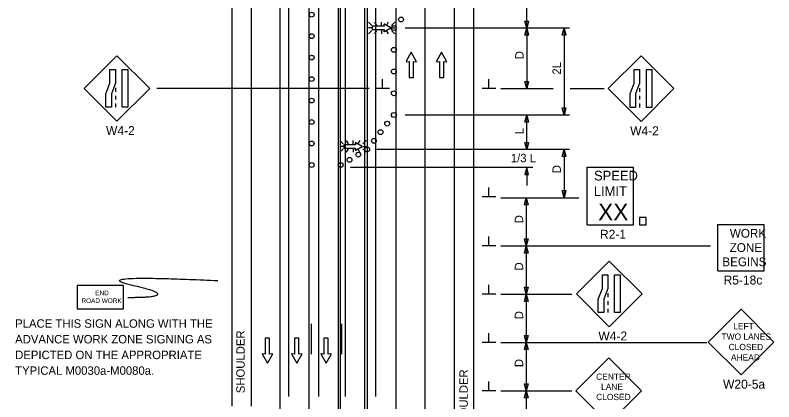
# Model space of a CAD drawing. Extents: x 16732 to 18475, y 6994 to 8262.
# Drawn here: x 16737 to 17365, y 7429 to 7749 of the extents above; entities that cross this region are included whole.
import ezdxf

# ---------------------------------------------------------------- set-up
doc = ezdxf.new("R2010")
doc.units = 0
for name, color, linetype in [('ALI_LEGAL_EX', 7, 'Continuous'), ('MT_SCRATCH_LEVEL_E', 7, 'Continuous'), ('PAVT_EDGE_EX', 7, 'Continuous'), ('TRAFFIC_SIGNS_PR', 7, 'Continuous'), ('TYPICAL_TEXT_DIMEN_PR', 7, 'Continuous')]:
    doc.layers.add(name, color=color, linetype=linetype)

msp = doc.modelspace()

# ---------------------------------------------------------------- linework, layer by layer
at = {"layer": 'ALI_LEGAL_EX'}
for p, q in [((16956.31, 7350.48), (16956.31, 8147.76)), ((16980.31, 7350.48), (16980.31, 8147.76)), ((17006.31, 7350.48), (17006.31, 8147.76)), ((17026.31, 7350.48), (17026.31, 8147.76)), ((17052.31, 7350.48), (17052.31, 8147.76)), ((17076.31, 7350.48), (17076.31, 8147.76))]:
    msp.add_line(p, q, dxfattribs=at)
for points in [[(16956.31, 7650.48), (16956.31, 7675.48)], [(16980.31, 7650.48), (16980.31, 7675.48)], [(17006.31, 7650.48), (17006.31, 7675.48)], [(17026.31, 7650.48), (17026.31, 7675.48)], [(17076.31, 7650.48), (17076.31, 7675.48)], [(16956.31, 7550.48), (16956.31, 7575.48)], [(16980.31, 7550.48), (16980.31, 7575.48)], [(17006.31, 7550.48), (17006.31, 7575.48)], [(17026.31, 7550.48), (17026.31, 7575.48)], [(17052.31, 7550.48), (17052.31, 7575.48)], [(17076.31, 7550.48), (17076.31, 7575.48)], [(16956.31, 7450.48), (16956.31, 7475.48)], [(16980.31, 7450.48), (16980.31, 7475.48)], [(17006.31, 7450.48), (17006.31, 7475.48)], [(17026.31, 7450.48), (17026.31, 7475.48)], [(17052.31, 7450.48), (17052.31, 7475.48)], [(17076.31, 7450.48), (17076.31, 7475.48)]]:
    msp.add_lwpolyline(points, dxfattribs=at)
at = {"layer": 'MT_SCRATCH_LEVEL_E'}
for p, q in [((17064.83, 7718.14), (17060.72, 7710.9)), ((17064.83, 7718.14), (17060.72, 7710.9)), ((17068.98, 7710.9), (17064.83, 7718.14)), ((17068.98, 7710.9), (17064.83, 7718.14)), ((17089.92, 7718.14), (17085.81, 7710.9)), ((17089.92, 7718.14), (17085.81, 7710.9)), ((17094.07, 7710.9), (17089.92, 7718.14)), ((17094.07, 7710.9), (17089.92, 7718.14)), ((17061.2, 7710.21), (17062.98, 7710.53)), ((17061.2, 7710.21), (17062.98, 7710.53)), ((17062.98, 7710.53), (17062.98, 7697.27)), ((17062.98, 7710.53), (17062.98, 7697.27)), ((17066.72, 7697.27), (17066.72, 7710.53)), ((17066.72, 7710.53), (17068.5, 7710.21)), ((17066.72, 7697.27), (17066.72, 7710.53)), ((17066.72, 7710.53), (17068.5, 7710.21)), ((17086.29, 7710.21), (17088.07, 7710.53)), ((17086.29, 7710.21), (17088.07, 7710.53)), ((17088.07, 7710.53), (17088.07, 7697.27)), ((17088.07, 7710.53), (17088.07, 7697.27)), ((17091.81, 7697.27), (17091.81, 7710.53)), ((17091.81, 7710.53), (17093.59, 7710.21)), ((17091.81, 7697.27), (17091.81, 7710.53)), ((17091.81, 7710.53), (17093.59, 7710.21)), ((17062.98, 7697.27), (17066.72, 7697.27)), ((17062.98, 7697.27), (17066.72, 7697.27)), ((17088.07, 7697.27), (17091.81, 7697.27)), ((17088.07, 7697.27), (17091.81, 7697.27)), ((16947.65, 7481.37), (16943.91, 7481.37)), ((16943.91, 7481.37), (16943.91, 7468.11)), ((16947.65, 7481.37), (16943.91, 7481.37)), ((16943.91, 7481.37), (16943.91, 7468.11)), ((16947.65, 7468.11), (16947.65, 7481.37)), ((16947.65, 7468.11), (16947.65, 7481.37)), ((16971.91, 7481.37), (16968.16, 7481.37)), ((16968.16, 7481.37), (16968.16, 7468.11)), ((16971.91, 7481.37), (16968.16, 7481.37)), ((16968.16, 7481.37), (16968.16, 7468.11)), ((16971.91, 7468.11), (16971.91, 7481.37)), ((16971.91, 7468.11), (16971.91, 7481.37)), ((16996.16, 7481.37), (16992.42, 7481.37)), ((16992.42, 7481.37), (16992.42, 7468.11)), ((16996.16, 7481.37), (16992.42, 7481.37)), ((16992.42, 7481.37), (16992.42, 7468.11)), ((16996.16, 7468.11), (16996.16, 7481.37)), ((16996.16, 7468.11), (16996.16, 7481.37)), ((16943.91, 7468.11), (16942.13, 7468.43)), ((16943.91, 7468.11), (16942.13, 7468.43)), ((16949.43, 7468.43), (16947.65, 7468.11)), ((16949.43, 7468.43), (16947.65, 7468.11)), ((16968.16, 7468.11), (16966.39, 7468.43)), ((16968.16, 7468.11), (16966.39, 7468.43)), ((16973.68, 7468.43), (16971.91, 7468.11)), ((16973.68, 7468.43), (16971.91, 7468.11)), ((16992.42, 7468.11), (16990.64, 7468.43)), ((16992.42, 7468.11), (16990.64, 7468.43)), ((16997.94, 7468.43), (16996.16, 7468.11)), ((16997.94, 7468.43), (16996.16, 7468.11)), ((16941.65, 7467.74), (16945.8, 7460.5)), ((16941.65, 7467.74), (16945.8, 7460.5)), ((16945.8, 7460.5), (16949.91, 7467.74)), ((16945.8, 7460.5), (16949.91, 7467.74)), ((16965.91, 7467.74), (16970.05, 7460.5)), ((16965.91, 7467.74), (16970.05, 7460.5)), ((16970.05, 7460.5), (16974.16, 7467.74)), ((16970.05, 7460.5), (16974.16, 7467.74)), ((16990.16, 7467.74), (16994.31, 7460.5)), ((16990.16, 7467.74), (16994.31, 7460.5)), ((16994.31, 7460.5), (16998.42, 7467.74)), ((16994.31, 7460.5), (16998.42, 7467.74))]:
    msp.add_line(p, q, dxfattribs=at)
for centre, start, end in [((17061.13, 7710.67), 150.42484, 279.96381), ((17061.13, 7710.67), 150.42484, 279.96381), ((17068.57, 7710.67), 260.03619, 29.77312), ((17068.57, 7710.67), 260.03619, 29.77312), ((17086.22, 7710.67), 150.42484, 279.96381), ((17086.22, 7710.67), 150.42484, 279.96381), ((17093.66, 7710.67), 260.03619, 29.77312), ((17093.66, 7710.67), 260.03619, 29.77312), ((16942.06, 7467.97), 80.03619, 209.77312), ((16942.06, 7467.97), 80.03619, 209.77312), ((16949.5, 7467.97), 330.42484, 99.96381), ((16949.5, 7467.97), 330.42484, 99.96381), ((16966.32, 7467.97), 80.03619, 209.77312), ((16966.32, 7467.97), 80.03619, 209.77312), ((16973.76, 7467.97), 330.42484, 99.96381), ((16973.76, 7467.97), 330.42484, 99.96381), ((16990.57, 7467.97), 80.03619, 209.77312), ((16990.57, 7467.97), 80.03619, 209.77312), ((16998.01, 7467.97), 330.42484, 99.96381), ((16998.01, 7467.97), 330.42484, 99.96381)]:
    msp.add_arc(centre, 0.463, start, end, dxfattribs=at)
at = {"layer": 'PAVT_EDGE_EX'}
for p, q in [((16963.15, 8262.34), (16963.15, 7433.15)), ((16988.15, 8262.34), (16988.15, 7433.15)), ((17010.15, 8262.34), (17010.15, 7433.15)), ((17035.15, 8262.34), (17035.15, 7433.15)), ((16916.31, 8206.5), (16916.31, 7425.05)), ((16932.31, 8206.5), (16932.31, 7425.05)), ((17004.31, 8206.5), (17004.31, 7350.48)), ((17028.31, 8206.5), (17028.31, 7350.48)), ((17100.31, 8206.5), (17100.31, 7350.48)), ((17116.31, 8206.5), (17116.31, 7350.48))]:
    msp.add_line(p, q, dxfattribs=at)
for points in [[(16982.24, 7468.16), (16982.24, 7493.16)], [(17007.24, 7468.16), (17007.24, 7493.16)]]:
    msp.add_lwpolyline(points, dxfattribs=at)
at = {"layer": 'TRAFFIC_SIGNS_PR'}
for p, q in [((17032.16, 7740.31), (17029.33, 7743.13)), ((17032.16, 7738.28), (17029.33, 7738.28)), ((17034.45, 7743.13), (17036.08, 7740.31)), ((17040.24, 7740.31), (17040.24, 7743.13)), ((17045.71, 7743.13), (17044.5, 7741.03)), ((17051.15, 7743.12), (17048.33, 7740.31)), ((17048.33, 7738.28), (17051.15, 7738.28)), ((17032.16, 7736.24), (17029.33, 7733.42)), ((17036.11, 7736.24), (17034.48, 7733.42)), ((17040.24, 7736.24), (17040.24, 7733.42)), ((17044.42, 7735.61), (17045.69, 7733.42)), ((17051.15, 7733.43), (17048.33, 7736.24)), ((16821.33, 7715.27), (16794.17, 7688.12)), ((16848.48, 7688.12), (16821.33, 7715.27)), ((17254.9, 7715.17), (17227.75, 7688.02)), ((17282.06, 7688.02), (17254.9, 7715.17)), ((16794.17, 7688.12), (16821.33, 7660.96)), ((16820.08, 7688.61), (16820.08, 7685.41)), ((16821.33, 7660.96), (16848.48, 7688.12)), ((17227.75, 7688.02), (17254.9, 7660.87)), ((17253.66, 7688.51), (17253.66, 7685.31)), ((17254.9, 7660.87), (17282.06, 7688.02)), ((16820.08, 7682.21), (16820.08, 7679.01)), ((17253.66, 7682.11), (17253.66, 7678.91)), ((16820.08, 7675.81), (16820.08, 7672.61)), ((17253.66, 7675.71), (17253.66, 7672.51)), ((17008.58, 7642.22), (17005.75, 7645.04)), ((17010.87, 7645.04), (17012.5, 7642.22)), ((17016.66, 7642.22), (17016.66, 7645.04)), ((17022.13, 7645.04), (17020.92, 7642.95)), ((17027.56, 7645.04), (17024.74, 7642.22)), ((17008.58, 7640.19), (17005.75, 7640.19)), ((17008.58, 7638.16), (17005.75, 7635.34)), ((17012.53, 7638.16), (17010.9, 7635.34)), ((17016.66, 7638.16), (17016.66, 7635.34)), ((17024.74, 7640.19), (17027.56, 7640.19)), ((17027.56, 7635.34), (17024.74, 7638.16)), ((17020.84, 7637.52), (17022.1, 7635.34)), ((17210.25, 7623.1), (17248.65, 7623.1)), ((17210.25, 7575.1), (17210.25, 7623.1)), ((17248.65, 7575.1), (17248.65, 7623.1)), ((17210.25, 7575.1), (17248.65, 7575.1)), ((17318.32, 7537.23), (17318.32, 7575.63)), ((17318.32, 7575.63), (17356.72, 7575.63)), ((17356.72, 7537.23), (17356.72, 7575.63)), ((17228.62, 7545.16), (17201.47, 7518.01)), ((17255.77, 7518.01), (17228.62, 7545.16)), ((17318.32, 7537.23), (17356.72, 7537.23)), ((17227.37, 7518.5), (17227.37, 7515.3)), ((17201.47, 7518.01), (17228.62, 7490.86)), ((17227.37, 7512.1), (17227.37, 7508.9)), ((17228.62, 7490.86), (17255.77, 7518.01)), ((17227.37, 7505.7), (17227.37, 7502.5)), ((17337.57, 7505.24), (17310.41, 7478.09)), ((17364.72, 7478.09), (17337.57, 7505.24)), ((17310.41, 7478.09), (17337.57, 7450.93)), ((17337.57, 7450.93), (17364.72, 7478.09)), ((17228.16, 7464.98), (17201, 7437.82)), ((17255.31, 7437.82), (17228.16, 7464.98)), ((17201, 7437.82), (17228.16, 7410.67)), ((17228.16, 7410.67), (17255.31, 7437.82))]:
    msp.add_line(p, q, dxfattribs=at)
for points in [[(17042.07, 7740.96), (17042.3, 7739.66), (17032.58, 7739.66), (17032.58, 7736.92), (17042.3, 7736.92), (17042.07, 7735.61)], [(17042.57, 7735.26), (17047.88, 7738.28), (17042.57, 7741.32)], [(17018.49, 7642.87), (17018.72, 7641.58), (17008.99, 7641.58), (17008.99, 7638.83), (17018.72, 7638.83), (17018.49, 7637.53)], [(17018.99, 7637.18), (17024.3, 7640.19), (17018.99, 7643.23)]]:
    msp.add_lwpolyline(points, dxfattribs=at)
for points in [[(16820.08, 7703.85), (16820.08, 7692.67), (16816.74, 7683.79), (16816.74, 7672.61), (16812.24, 7672.61), (16812.24, 7683.79), (16815.59, 7692.67), (16815.59, 7703.85)], [(16830.22, 7703.85), (16830.22, 7672.61), (16825.72, 7672.61), (16825.72, 7703.85)], [(17253.66, 7703.76), (17253.66, 7692.58), (17250.31, 7683.69), (17250.31, 7672.51), (17245.82, 7672.51), (17245.82, 7683.69), (17249.16, 7692.58), (17249.16, 7703.76)], [(17263.79, 7703.76), (17263.79, 7672.51), (17259.3, 7672.51), (17259.3, 7703.76)], [(17253.66, 7575.1), (17259.25, 7575.1), (17259.25, 7581.27), (17253.66, 7581.27)], [(17227.37, 7533.75), (17227.37, 7522.56), (17224.03, 7513.68), (17224.03, 7502.5), (17219.54, 7502.5), (17219.54, 7513.68), (17222.88, 7522.56), (17222.88, 7533.75)], [(17237.51, 7533.75), (17237.51, 7502.5), (17233.02, 7502.5), (17233.02, 7533.75)], [(16788.41, 7505.76), (16826.81, 7505.76), (16826.81, 7524.96), (16788.41, 7524.96)]]:
    msp.add_lwpolyline(points, close=True, dxfattribs=at)
for centre in [(16982.41, 7749.34), (17056.38, 7745.35), (17050.38, 7738.2), (16982.41, 7731.54), (17050.38, 7720.2), (16982.41, 7713.75), (17050.38, 7702.2), (16982.41, 7695.95), (17050.38, 7684.2), (16982.41, 7678.16), (17050.38, 7666.2), (16982.41, 7660.36), (17044.88, 7659.07), (17039.39, 7651.94), (16982.41, 7642.57), (17033.89, 7644.82), (17028.39, 7637.69), (17021.06, 7633.39), (16982.41, 7624.77), (17006.41, 7624.77), (17013.73, 7629.08)]:
    msp.add_circle(centre, 2, dxfattribs=at)
for centre, start, end in [((17042.4, 7741.02), 61.48329, 189.95933), ((17042.4, 7735.56), 170.73078, 298.89165), ((17018.82, 7642.93), 61.48329, 189.95933), ((17018.82, 7637.48), 170.73078, 298.89165)]:
    msp.add_arc(centre, 0.341, start, end, dxfattribs=at)
msp.add_open_spline([(16830.4, 7515.13), (16877.64, 7515.13), (16792.62, 7534.48), (16904.91, 7528.99)], degree=2, dxfattribs=at)
at = {"layer": 'TYPICAL_TEXT_DIMEN_PR'}
for p, q in [((17160.31, 7738.19), (17160.31, 7768.77)), ((17195.67, 7738.19), (17059.67, 7738.19)), ((17160.31, 7738.19), (17158.74, 7744.06)), ((17158.74, 7744.06), (17160.31, 7744.06)), ((17158.74, 7732.33), (17160.31, 7738.19)), ((17160.31, 7744.06), (17161.88, 7744.06)), ((17161.88, 7744.06), (17160.31, 7738.19)), ((17160.31, 7738.19), (17160.31, 7688.19)), ((17160.31, 7738.19), (17161.88, 7732.33)), ((17189.59, 7732.33), (17191.16, 7738.19)), ((17191.16, 7738.19), (17191.16, 7666.2)), ((17191.16, 7738.19), (17192.73, 7732.33)), ((17160.31, 7732.33), (17158.74, 7732.33)), ((17161.88, 7732.33), (17160.31, 7732.33)), ((17191.16, 7732.33), (17189.59, 7732.33)), ((17192.73, 7732.33), (17191.16, 7732.33)), ((17041.1, 7688.19), (17041.1, 7695.98)), ((17129.06, 7688.19), (17129.06, 7695.98)), ((17160.31, 7688.19), (17158.74, 7694.06)), ((17158.74, 7694.06), (17160.31, 7694.06)), ((17160.31, 7694.06), (17161.88, 7694.06)), ((17161.88, 7694.06), (17160.31, 7688.19)), ((17030.02, 7688.19), (16854.31, 7688.19)), ((17046.73, 7688.19), (17035.48, 7688.19)), ((17134.69, 7688.19), (17123.44, 7688.19)), ((17138.94, 7688.19), (17182.14, 7688.19)), ((17196.21, 7688.19), (17224.34, 7688.19)), ((17191.16, 7666.2), (17189.59, 7672.07)), ((17189.59, 7672.07), (17191.16, 7672.07)), ((17191.16, 7672.07), (17192.73, 7672.07)), ((17192.73, 7672.07), (17191.16, 7666.2)), ((17195.67, 7666.2), (17059.67, 7666.2)), ((17158.74, 7660.34), (17160.31, 7666.2)), ((17160.31, 7637.69), (17160.31, 7666.2)), ((17160.31, 7666.2), (17161.88, 7660.34)), ((17160.31, 7660.34), (17158.74, 7660.34)), ((17161.88, 7660.34), (17160.31, 7660.34)), ((17195.67, 7637.69), (17036.26, 7637.69)), ((17160.31, 7637.69), (17158.74, 7643.55)), ((17158.74, 7643.55), (17160.31, 7643.55)), ((17160.31, 7643.55), (17161.88, 7643.55)), ((17161.88, 7643.55), (17160.31, 7637.69)), ((17189.59, 7631.83), (17191.16, 7637.69)), ((17191.16, 7637.69), (17192.73, 7631.83)), ((17191.16, 7637.69), (17191.16, 7597.69)), ((17191.16, 7631.83), (17189.59, 7631.83)), ((17192.73, 7631.83), (17191.16, 7631.83)), ((17165.31, 7622.77), (17014.53, 7622.77)), ((17160.31, 7622.77), (17158.74, 7616.91)), ((17160.31, 7622.77), (17160.31, 7607.85)), ((17161.88, 7616.91), (17160.31, 7622.77)), ((17158.74, 7616.91), (17160.31, 7616.91)), ((17160.31, 7616.91), (17161.88, 7616.91)), ((17129.06, 7598.34), (17129.06, 7606.13)), ((17191.16, 7597.69), (17189.59, 7603.55)), ((17189.59, 7603.55), (17191.16, 7603.55)), ((17191.16, 7603.55), (17192.73, 7603.55)), ((17192.73, 7603.55), (17191.16, 7597.69)), ((17134.69, 7598.34), (17123.44, 7598.34)), ((17138.94, 7597.69), (17203.28, 7597.69)), ((17158.37, 7591.83), (17159.94, 7597.69)), ((17159.94, 7597.69), (17159.94, 7557.69)), ((17159.94, 7597.69), (17161.51, 7591.83)), ((17159.94, 7591.83), (17158.37, 7591.83)), ((17161.51, 7591.83), (17159.94, 7591.83)), ((17129.06, 7557.69), (17129.06, 7565.48)), ((17159.94, 7557.69), (17158.37, 7563.55)), ((17158.37, 7563.55), (17159.94, 7563.55)), ((17159.94, 7563.55), (17161.51, 7563.55)), ((17161.51, 7563.55), (17159.94, 7557.69)), ((17134.69, 7557.69), (17123.44, 7557.69)), ((17138.94, 7557.69), (17312.45, 7557.69)), ((17158.37, 7551.83), (17159.94, 7557.69)), ((17159.94, 7557.69), (17159.94, 7517.69)), ((17159.94, 7557.69), (17161.51, 7551.83)), ((17159.94, 7551.83), (17158.37, 7551.83)), ((17161.51, 7551.83), (17159.94, 7551.83)), ((17129.06, 7517.69), (17129.06, 7525.48)), ((17159.94, 7517.69), (17158.37, 7523.55)), ((17158.37, 7523.55), (17159.94, 7523.55)), ((17159.94, 7523.55), (17161.51, 7523.55)), ((17161.51, 7523.55), (17159.94, 7517.69)), ((17134.69, 7517.69), (17123.44, 7517.69)), ((17138.94, 7517.69), (17197.62, 7517.69)), ((17158.37, 7511.83), (17159.94, 7517.69)), ((17159.94, 7517.69), (17159.94, 7477.69)), ((17159.94, 7517.69), (17161.51, 7511.83)), ((17159.94, 7511.83), (17158.37, 7511.83)), ((17161.51, 7511.83), (17159.94, 7511.83)), ((17129.06, 7477.69), (17129.06, 7485.48)), ((17159.94, 7477.69), (17158.37, 7483.55)), ((17158.37, 7483.55), (17159.94, 7483.55)), ((17159.94, 7483.55), (17161.51, 7483.55)), ((17161.51, 7483.55), (17159.94, 7477.69)), ((17134.69, 7477.69), (17123.44, 7477.69)), ((17138.94, 7477.69), (17309.22, 7477.69)), ((17158.37, 7471.83), (17159.94, 7477.69)), ((17159.94, 7477.69), (17159.94, 7437.69)), ((17159.94, 7477.69), (17161.51, 7471.83)), ((17159.94, 7471.83), (17158.37, 7471.83)), ((17161.51, 7471.83), (17159.94, 7471.83)), ((17129.06, 7437.69), (17129.06, 7445.48)), ((17159.94, 7437.69), (17158.37, 7443.55)), ((17158.37, 7443.55), (17159.94, 7443.55)), ((17159.94, 7443.55), (17161.51, 7443.55)), ((17161.51, 7443.55), (17159.94, 7437.69)), ((17134.69, 7437.69), (17123.44, 7437.69)), ((17138.94, 7437.69), (17197.62, 7437.69)), ((17158.37, 7431.83), (17159.94, 7437.69)), ((17159.94, 7437.69), (17159.94, 7397.69)), ((17159.94, 7437.69), (17161.51, 7431.83)), ((17159.94, 7431.83), (17158.37, 7431.83)), ((17161.51, 7431.83), (17159.94, 7431.83))]:
    msp.add_line(p, q, dxfattribs=at)

# ---------------------------------------------------------------- texts
at = {"layer": 'TRAFFIC_SIGNS_PR'}
for s, height, p in [('W4-2', 7.44, (16812.28, 7649.52)), ('W4-2', 7.44, (17245.86, 7649.43)), ('SPEED', 8, (17216.01, 7611.96)), ('LIMIT', 8, (17215.85, 7599.16)), ('XX', 14.031, (17219.36, 7578.86)), ('R2-1', 7.44, (17220.92, 7563.66)), ('WORK', 7.217, (17328.32, 7564.6)), ('ZONE', 7.217, (17328.2, 7552.79)), ('BEGINS', 7.217, (17322.13, 7540.98)), ('R5-18c', 7.44, (17323.13, 7525.79)), ('END', 3.831, (16803.41, 7516.89)), ('ROAD WORK', 3.831, (16792.02, 7510.5)), ('PLACE THIS SIGN ALONG WITH THE', 7, (16737.13, 7489.98)), ('LEFT', 5.2, (17331.1, 7488.62)), ('W4-2', 7.44, (17219.58, 7479.42)), ('ADVANCE WORK ZONE SIGNING AS', 7, (16737.13, 7476.98)), ('TWO LANES', 5.2, (17321.43, 7480.02)), ('CLOSED', 5.2, (17327.28, 7471.42)), ('DEPICTED ON THE APPROPRIATE', 7, (16737.13, 7463.98)), ('AHEAD', 5.2, (17329.23, 7462.82)), ('TYPICAL M0030a-M0080a.', 7, (16737.13, 7450.98)), ('W20-5a', 7.44, (17322.71, 7439.49))]:
    msp.add_text(s, height=height, dxfattribs=at).set_placement(p)
at = {"layer": 'TYPICAL_TEXT_DIMEN_PR'}
for s, p in [('D', (17157.75, 7712.41)), ('2L', (17188.6, 7699.64)), ('L', (17157.75, 7650.34)), ('D', (17188.6, 7618)), ('D', (17157.38, 7576.49)), ('D', (17157.38, 7537.37)), ('D', (17157.38, 7497.05)), ('SHOULDER', (16927.04, 7435.74)), ('D', (17157.38, 7457.37)), ('SHOULDER', (17111.59, 7403.51))]:
    msp.add_text(s, height=7, rotation=90, dxfattribs=at).set_placement(p)
for s, height, p in [('1/3 L', 7, (17147.15, 7627.01)), ('CENTER', 5.2, (17217.73, 7446.83)), ('LANE', 5.2, (17221.81, 7438.43)), ('CLOSED', 5.2, (17217.73, 7430.03))]:
    msp.add_text(s, height=height, dxfattribs=at).set_placement(p)

doc.saveas('drawing.dxf')
